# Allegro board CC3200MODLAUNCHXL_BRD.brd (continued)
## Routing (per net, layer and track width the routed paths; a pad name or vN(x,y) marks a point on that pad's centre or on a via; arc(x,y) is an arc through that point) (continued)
CC_GPIO_07: length 91.3
  TOP w0.127: R339.1 44.55,35.38 v1(43.78,35.38) 41.58,35.38 41.2,35.76 U1.52 ; R31.1 1.57,24.89 2.34,25.65 14.94,25.65 v1(15.09,25.5) ; v1(9.11,49.68) 9.11,49.7 7.62,51.18 5.71,51.18 ; v1(43.69,26.54) 43.87,26.36 R300.1
  MID2(L3) w0.127: v1(43.69,26.54) 43.78,26.63 v1(43.78,35.38) ; v1(15.09,25.5) 15.09,26.36 13.86,27.6 13.86,34.72 10.92,37.66 10.92,43.05 9.27,44.7 9.27,49.52 v1(9.11,49.68)
  BOTTOM w0.127: v1(15.09,25.5) 15.38,25.78 15.38,25.79 15.82,26.24 43.38,26.24 v1(43.69,26.54)
CC_GPIO_08: length 35.4
  TOP w0.127: v1(13.34,27.08) 13.34,27.03 13.64,26.72 R278.2 ; U1.53 36.87,37.03 36.58,36.74 v1(36.58,36.48)
  MID2(L3) w0.127: v1(12.52,35.1) 13.34,34.29 v1(13.34,27.08)
  BOTTOM w0.127: v1(12.52,35.1) 12.73,35.31 19.46,35.31 20.8,36.65 36.41,36.65 v1(36.58,36.48)
CC_GPIO_09: length 67.3
  TOP w0.127: v1(43.29,34.49) 44.55,34.49 R334.1 ; v1(43.26,38.3) U1.54 ; R211.1 R212.2 21.72,9.62 v1(21.72,9.62) ; R291.2 14.56,21.89 v1(14.61,21.84)
  MID2(L3) w0.127: v1(43.26,38.3) 43.29,38.27 v1(43.29,34.49) ; v1(14.61,21.84) 14.61,21.8 14.53,21.73 14.53,15.24 20.14,9.62 v1(21.72,9.62)
  BOTTOM w0.127: v1(14.61,21.84) 14.39,22.06 14.39,25.74 15.57,26.92 20.83,26.92 21.37,27.45 37.23,27.45 43.29,33.52 v1(43.29,34.49)
CC_GPIO_10: length 126.1
  TOP w0.127: v1(3.02,20.78) 2.21,20.78 1.57,21.41 R289.1 ; v1(17.55,9.62) R213.2 R210.1 ; U1.3 34.9,40.74 35.26,41.09 36.68,41.09 v1(36.8,40.97) 36.93,41.09 38.41,41.09 40.39,39.12 44.42,39.12 R299.1
  MID2(L3) w0.127: J3.2 41.53,67.77 41.53,64.39 44.45,61.47 44.45,50.16 39.43,45.15 37.91,45.15 36.8,44.04 v1(36.8,40.97) ; v1(10.5,42.62) 10.67,42.45 10.67,37.55 13.6,34.62 13.6,27.42 14.35,26.67 14.35,24.18 12.65,22.48 v1(12.65,20.78) 12.65,10.97 14,9.62 v1(17.55,9.62)
  BOTTOM w0.127: v1(36.8,40.97) 35.36,42.41 26.62,42.41 25.79,41.58 24.03,41.58 22.99,42.62 v1(10.5,42.62) ; v1(12.65,20.78) v1(3.02,20.78)
CC_GPIO_11: length 117.4
  TOP w0.127: R209.1 R214.2 v1(13.72,10.91) ; R290.1 1.57,18.36 1.98,17.96 13.64,17.96 v1(14.1,18.41) ; R298.1 43.33,43.08 41.19,40.94 v1(40.06,40.94) 38.92,40.94 38.48,41.39 34.2,41.39 33.63,40.81 U1.4
  MID2(L3) w0.127: v1(41.19,33.15) 40.87,33.15 40.05,33.97 40.05,40.93 v1(40.06,40.94) 40.26,41.14 40.26,45.59 44.7,50.04 44.7,61.72 41.78,64.64 41.78,70.56 J2.2 ; v1(13.72,10.91) 13.84,10.91 14.1,11.16 v1(14.1,18.41)
  BOTTOM w0.127: v1(41.19,33.15) 41.14,33.15 37.91,29.92 23.47,29.92 20.73,27.18 15.46,27.18 14.14,25.85 14.14,20.26 14.1,20.22 v1(14.1,18.41)
CC_GPIO_12: length 32.2
  TOP w0.127: U1.9 27.28,41.05 26.67,41.66 v1(26.5,41.66) ; R288.1 1.57,35.05 2.03,35.51 v1(3.05,35.51)
  BOTTOM w0.127: v1(3.05,35.51) 4.88,37.34 4.88,39.7 6.22,41.05 12.33,41.05 13.32,42.04 13.34,42.04 13.66,42.36 22.88,42.36 23.92,41.33 26.16,41.33 26.49,41.66 v1(26.5,41.66)
CC_GPIO_13: length 130.9
  TOP w0.127: R287.1 1.57,37.52 2.41,38.35 12.55,38.35 v1(13.74,39.54) ; R111.2 46.84,72.9 42.42,72.9 41.53,72.01 41.53,67.26 J4.1 ; U1.10 26.01,41.61 v1(25.62,42) ; v1(13.68,11.56) 12.57,10.45 12.57,8.76 11.76,7.95 R208.1 SW3.T1
  MID2(L3) w0.127: J4.1 44.3,65.81 47.5,62.61 47.5,50.42 44.2,47.12 44.2,43.69 43.56,43.05 v1(43.56,42.04) ; v1(14.1,43.05) 14.06,43.05 13.74,42.73 v1(13.74,39.54) 13.74,37.44 14.52,36.66 14.52,36.66 14.77,36.42 14.77,36.41 16.76,34.42 16.76,33.3 15.84,32.38 15.84,24.09 13.68,21.93 v1(13.68,11.56)
  BOTTOM w0.127: v1(43.56,42.04) 43.31,42.29 35.94,42.29 35.56,42.67 26.29,42.67 v1(25.62,42) 23.97,42 23.09,42.87 14.28,42.87 v1(14.1,43.05)
CC_GPIO_14: length 45.9
  TOP w0.127: R237.1 1.57,27.48 2.26,28.17 16.31,28.17 v1(16.76,28.62) ; U1.5 32.36,40.87 v1(32.13,41.09)
  MID2(L3) w0.127: v1(16.76,28.62) 16.76,32.3 17.27,32.81 17.27,41.73 v1(17.22,41.78)
  BOTTOM w0.127: v1(17.22,41.78) 17.38,41.95 22.9,41.95 23.77,41.07 32.11,41.07 v1(32.13,41.09)
CC_GPIO_15: length 44.7
  TOP w0.127: R294.2 57.56,27.63 57.56,29.79 R296.2 56.92,30.84 v1(56.64,31.11) ; v1(56.64,43) 55.37,43 54.81,43.56 43.43,43.56 41.27,41.4 38.82,41.4 38.58,41.64 31.79,41.64 31.09,40.94 U1.6
  MID2(L3) w0.127: v1(56.64,43) 56.82,42.82 56.82,31.29 v1(56.64,31.11)
CC_GPIO_16: length 46
  TOP w0.127: U1.7 29.82,40.94 30.77,41.89 38.69,41.89 38.92,41.66 41.15,41.66 43.31,43.81 55.24,43.81 55.52,43.54 v1(56.9,43.54) ; R293.2 56.92,28.75 v1(56.9,28.73) 56.92,28.7 R297.2
  MID2(L3) w0.127: v1(56.9,43.54) 57.07,43.36 57.07,28.91 v1(56.9,28.73)
CC_GPIO_17: length 37.4
  TOP w0.127: R280.2 56.92,37.26 56.39,37.8 v1(56.36,37.8) ; v1(56.16,44.04) 56.13,44.07 43.18,44.07 41.02,41.91 39.03,41.91 38.79,42.15 29.7,42.15 28.55,41 U1.8
  MID2(L3) w0.127: v1(56.36,37.8) 56.36,37.97 55.96,38.38 55.96,43.84 v1(56.16,44.04)
CC_GPIO_22: length 84.9
  TOP w0.127: v1(45.39,44.5) 43.23,44.5 40.92,42.19 39.11,42.19 38.9,42.4 29.61,42.4 29.6,42.42 25.32,42.42 24.74,41.84 U1.11 ; SW2.T1 50.06,1.54 44.97,1.54 R207.1 44.68,1.83 v1(44.68,2.54) ; v1(45.39,17.73) 56.16,17.73 56.92,18.49 R313.2
  MID2(L3) w0.127: v1(45.39,44.5) v1(45.39,17.73) 45.39,17.6 44.68,16.89 v1(44.68,2.54)
CC_GPIO_23: length 54.3
  TOP w0.127: v1(39.22,42.75) 39.14,42.67 23.7,42.67 23.47,42.44 ; 23.47,42.44 17.65,48.26 J10.2 ; 23.47,42.44 U1.12 ; R310.1 v1(41.43,21.89)
  MID2(L3) w0.127: v1(39.22,42.75) 39.37,42.59 39.37,33.99 39.38,33.98 39.38,33.88 41.4,31.86 41.4,21.92 v1(41.43,21.89)
CC_GPIO_24: length 67.5
  TOP w0.127: v1(19.12,37.16) 19.09,37.16 18.96,37.03 U1.18 16.69,37.03 16.15,37.57 16.15,51.21 17.14,52.2 19.68,52.2 J11.2 ; R336.1 44.43,36.84 v1(41.66,36.84) ; v1(43.32,19.3) R311.1
  MID2(L3) w0.127: v1(41.66,36.84) 41.66,33.66 42.23,33.08 42.23,30.61 42.6,30.23 42.6,26.08 43.32,25.36 v1(43.32,19.3)
  BOTTOM w0.127: v1(19.12,37.16) 38.51,37.16 38.83,36.84 v1(41.66,36.84)
CC_GPIO_26: length 66.8
  TOP w0.127: v1(44.02,42.55) 44.37,42.19 R285.1 ; v1(23.41,43.78) 21.97,45.21 21.97,51.44 20.95,52.45 9.55,52.45 5.74,56.26 J5.3 ; v1(19.2,28.27) 19.08,28.14 U1.25
  MID2(L3) w0.127: v1(23.41,43.78) 22.86,43.23 22.86,31.7 19.43,28.27 v1(19.2,28.27)
  BOTTOM w0.127: v1(44.02,42.55) 40.5,42.55 39.88,43.16 24.02,43.16 v1(23.41,43.78)
CC_GPIO_27: length 71.4
  TOP w0.127: R286.1 44.23,40.2 44.2,40.21 v1(41.66,40.21) ; U1.26 18.41,26.87 v1(19.18,27.63) ; J5.4 5.71,58.17 11.18,52.7 21.08,52.7 22.23,51.56 22.23,45.59 v1(24.13,43.69)
  MID2(L3) w0.127: v1(24.13,43.69) 23.11,42.67 23.11,31.57 v1(19.18,27.63) ; v1(41.06,42.96) 41.66,42.37 v1(41.66,40.21)
  BOTTOM w0.127: v1(41.06,42.96) 40.59,42.96 40.13,43.42 24.4,43.42 v1(24.13,43.69)
CC_GPIO_28: length 50.2
  TOP w0.127: R308.1 v1(43.31,29.46) ; v1(42.88,37.52) 43.74,37.52 44.07,37.85 48.44,37.85 49.02,38.43 55.98,38.43 56.39,38.84 56.41,38.84 56.92,39.34 R295.2 ; U1.19 v1(19.12,35.76)
  MID2(L3) w0.127: v1(42.88,37.52) 42.84,37.48 v1(42.84,36.37) 42.82,36.36 42.82,34.37 43.48,33.71 43.48,29.64 v1(43.31,29.46)
  BOTTOM w0.127: v1(42.84,36.37) 38.94,36.37 38.41,36.9 20.26,36.9 v1(19.12,35.76)
CC_GPIO_30: length 24.5
  TOP w0.127: U1.42 36.17,24.54 v1(35.94,24.77) ; R279.2 v1(16.26,24.43)
  BOTTOM w0.127: v1(35.94,24.77) 34.72,25.98 17.85,25.98 16.3,24.43 v1(16.26,24.43)
CC_NRESET: length 99.2
  TOP w0.127: R113.1 15.77,64.77 v1(16.89,64.77) ; U1.35 v1(27.28,24.66) ; v1(43.56,81.41) 43.56,82.08 D9.2 47.07,83.86 SW1.T2 48.68,86.96 47.09,88.55 Q10.1
  MID2(L3) w0.127: v1(27.28,24.66) 27.28,57.25 28.45,58.42 v1(28.45,63.65) ; v1(43.56,81.41) 43.56,77.9 39.12,73.46 39.12,63.75 v1(39.37,63.5)
  BOTTOM w0.127: v1(16.89,64.77) 17.65,64.77 18.92,63.5 28.27,63.5 28.42,63.65 v1(28.45,63.65) 28.6,63.5 v1(39.37,63.5)
DBG_RST_N: length 9
  TOP w0.127: v1(14.61,68.07) 13.08,68.07 12.05,67.04 U9.10 ; U5.19 16.08,70.67 R314.2 16.03,70.26 15.75,69.98 14.99,69.98 14.73,69.72 v1(14.61,69.72)
  BOTTOM w0.127: v1(14.61,69.72) v1(14.61,68.07)
DBGENN: length 26.1
  TOP w0.127: 9.17,81.44 9.11,81.44 8.46,82.09 8.38,82.09 ; 9.17,81.44 8.23,80.49 ; 9.17,81.44 U4.13 ; R317.2 15.11,71.5 v1(14.73,71.88) ; 8.38,82.09 8.69,82.39 R326.2 ; 8.38,82.09 U4.1 ; v1(13.21,78.74) 12.93,79.02 R315.2 12.82,79.49 U4.10 9.26,79.49 8.26,80.49 8.23,80.49 ; 8.23,80.49 8.23,80.49 7.87,80.14 U4.4
  BOTTOM w0.127: v1(13.21,78.74) 14.61,77.34 14.61,72.01 v1(14.73,71.88)
DBGMOD: length 17.6
  TOP w0.127: U4.2 v1(7.26,81.44) ; R316.2 14.86,72.75 14.86,74.04 12.95,75.95 12.95,76.64 12.38,77.22 10.03,77.22 7.76,79.49 v1(7.75,79.49) U4.5
  BOTTOM w0.127: v1(7.26,81.44) 7.75,80.95 v1(7.75,79.49)
FT_CS: length 16.4
  TOP w0.127: v1(10.26,72.11) U7.9 13.24,72.11 13.97,71.37 13.97,69.72 14.48,69.22 15.09,69.22 R306.2 ; v1(7.62,72.14) 7.62,67.94 6.72,67.04 U9.5
  BOTTOM w0.127: v1(7.62,72.14) 7.65,72.11 v1(10.26,72.11)
FT_DI: length 13.1
  TOP w0.127: U7.11 11.3,73.53 10.03,73.53 9.53,73.03 9.53,68.58 10.41,67.69 U9.11 12.06,67.69 12.95,68.58 15.09,68.58 R305.2
FT_DO: length 25.5
  TOP w0.127: v1(10.16,78.74) 10.26,78.84 U4.9 ; R304.2 13.46,67.44 v1(13.34,67.31) ; U7.2 4.67,74.71 4.32,75.06 4.32,76.33 4.83,76.83 7.49,76.83 v1(8.51,77.85)
  BOTTOM w0.127: v1(13.34,67.31) 13.34,67.56 12.19,68.71 12.19,75.16 11.18,76.17 11.18,77.72 v1(10.16,78.74) 9.4,78.74 v1(8.51,77.85)
FT_SK: length 19.9
  TOP w0.127: v1(14.99,65.76) R303.2 ; U4.12 9.97,80.79 v1(9.91,80.72)
  BOTTOM w0.127: v1(9.91,80.72) 12.45,78.18 12.45,68.83 14.99,66.29 v1(14.99,65.76)
FTDI_RX: length 6.5
  TOP w0.127: R330.2 25.39,61.94 25.39,63.49 27.76,65.87 R333.2
FTDI_TX: length 12.1
  TOP w0.127: R332.2 25.64,63.39 25.64,59.09 24.4,57.85 U11.4
JTAG_TCK: length 22
  TOP w0.127: v1(15.98,33.63) 16.39,33.22 U1.21 ; v1(11.56,47.93) R13.1 J8.2
  MID2(L3) w0.127: v1(11.56,47.93) 11.56,37.77 15.7,33.63 v1(15.98,33.63)
JTAG_TMS: length 22.7
  TOP w0.127: U1.22 18.54,31.95 19.13,32.54 19.13,33.63 18.9,33.86 17.2,33.86 15.9,35.15 15.9,50.14 J9.2
LP_GPIO_01: length 58.2
  TOP w0.127: R284.2 56.92,22.63 v1(56.87,22.68) ; v1(57.33,44.4) 56.77,44.96 43.18,44.96 41.87,43.65 31.53,43.65 28.85,46.33 28.85,50.52 J7.1
  MID2(L3) w0.127: v1(57.33,44.4) 57.33,23.14 v1(56.87,22.68)
LP_GPIO_02: length 19.1
  TOP w0.127: v1(14.22,37.95) 13.64,37.37 R309.2
  MID2(L3) w0.127: J6.1 24.41,51.18 14.22,41 v1(14.22,37.95)
LP_GPIO_25: length 43.3
  TOP w0.127: R36.2 56.92,24.89 56.16,25.65 44.09,25.65 v1(44.04,25.7) ; v1(43.07,31.67) 44.53,31.67 R337.1
  MID2(L3) w0.127: v1(44.04,25.7) 43.43,25.7 42.88,26.26 42.88,30.45 43.07,30.65 v1(43.07,31.67) 43.07,33.77 42.57,34.26 42.57,34.26 42.42,34.42 42.42,45.72 46.23,49.53 J14.1
LP_RESET_OUT: length 66.7
  TOP w0.127: D9.1 47.09,81.29 R226.2 47.12,78.87 v1(46.46,78.21) ; v1(44.86,32.66) 45.36,32.66 45.97,33.27 55.85,33.27 56.39,32.74 v1(56.39,32.72) 56.41,32.72 56.92,32.21 R292.2
  MID2(L3) w0.127: v1(46.46,78.21) 45.21,76.96 45.21,65.28 47.75,62.74 47.75,50.29 44.45,46.99 44.45,42.63 44.63,42.45 44.63,32.89 v1(44.86,32.66)
RF_BG: length 13.5
  TOP w0.508: U1.31 22.2,22.3 arc(22.44,19.8) 23.14,17.39 arc(24.09,15.47) 25.33,13.73 arc(25.7,13.32) 26.09,12.91 R75.1
SENS_I2C_SCL: length 12.2
  TOP w0.127: R172.1 R97.1 ; R172.1 49.25,69.44 49.91,70.1 51.59,70.1 R107.1 ; R172.1 47.12,68.45 46.71,68.86 J3.1
SENS_I2C_SDA: length 22.4
  TOP w0.127: R104.1 R173.1 48.79,65 46.35,67.44 42.55,67.44 41.78,68.2 41.78,70.71 J2.1 44.17,70.71 R108.1
SOP0: length 65.4
  TOP w0.127: v1(26.04,24.89) 26.01,24.87 U1.34 ; v1(53.47,55.79) 53.47,55.98 53.98,56.49 R4.1 54.61,55.98 54.61,52.84 J17.1
  MID2(L3) w0.127: v1(26.8,49.53) 26.92,49.4 26.92,25.78 v1(26.04,24.89)
  BOTTOM w0.127: v1(53.47,55.79) 53.34,55.92 30.64,55.92 29.46,54.75 29.46,50.67 28.32,49.53 v1(26.8,49.53)
SOP1: length 61.4
  TOP w0.127: v1(46.23,56.39) 46.33,56.49 R7.1 51.18,55.5 51.56,55.12 51.56,52.84 J16.1 ; U1.24 v1(19.26,29.41)
  MID2(L3) w0.127: v1(46.23,56.39) 44.96,55.12 44.96,49.91 40.51,45.47 40.51,40.05 40.35,39.89 40.35,34.28 40.84,33.78 v1(40.87,33.78)
  BOTTOM w0.127: v1(19.26,29.41) 20.06,30.21 37.84,30.21 40.77,33.14 40.77,33.68 v1(40.87,33.78)
SOP2/TCXO_EN: length 58.1
  TOP w0.127: v1(46.61,55.37) 47.24,56.01 R8.1 48.62,52.74 J15.1 ; R12.2 15.6,31.57 16.23,32.2 v1(16.26,32.2)
  MID2(L3) w0.127: v1(16.26,32.2) 17.02,32.97 17.02,41.26 16.76,41.52 16.76,42.24 23.24,48.72 v1(23.24,48.77)
  BOTTOM w0.127: v1(23.24,48.77) 27.94,48.77 29.72,50.55 29.72,54.64 30.7,55.63 46.35,55.63 v1(46.61,55.37)
SRSTN: length 0.8
  TOP w0.127: R327.2 R113.2
TEMP_INTR: length 4.6
  TOP w0.127: R111.1 49.4,71.88 50.42,72.9 50.42,74.17 50.93,74.68 U6.C2
USB_D+: length 18.4
  TOP w0.152: J1.3 v1(11.94,86.89) ; R28.1 21.59,78.64 21.59,79.2 21.71,79.32 21.84,79.32 ; v1(21.84,80.06) 21.84,79.32 ; 21.84,79.32 D14.1
  BOTTOM w0.152: v1(21.84,80.06) 21.62,79.83 21.62,79.39 21.25,79.02 18.05,79.02 12.13,84.93 12.13,86.7 v1(11.94,86.89)
USB_D-: length 17.4
  TOP w0.152: J1.2 v1(12.59,86.89) ; v1(21.09,80.04) 21.09,79.38 D13.1 21.19,79.32 21.31,79.2 21.31,78.64 R343.1
  BOTTOM w0.152: v1(21.09,80.04) 21.34,79.79 21.34,79.5 21.13,79.3 18.16,79.3 12.41,85.05 12.41,86.72 v1(12.59,86.89)
USB_DM: length 2.5
  TOP w0.152: R343.2 21.33,77.2 21.33,76.13 21.22,76.02 U5.8
USB_DP: length 6.3
  TOP w0.152: v1(22.48,77.52) R28.2 21.61,77.24 21.61,76.13 21.72,76.02 U5.7 ; R345.1 v1(24.56,78.46)
  BOTTOM w0.152: v1(24.56,78.46) 24.56,78.46 23.62,77.52 v1(22.48,77.52)
N185612: length 8.3
  TOP w0.127: R103.1 R98.1 53.07,68.95 U10.7 53.43,67.61 53.75,67.28 C50.1 54.23,65.64 53.51,64.92 C52.1 52.57,65.05 U10.3
N185801: length 3.5
  TOP w0.254: C51.1 54.95,74.18 U6.A3
  TOP w0.305: R101.1 C51.1
N186121: length 1.5
  TOP w0.127: R102.2 50.15,66 U10.1
N186159: length 2.1
  TOP w0.127: R103.2 51.16,67.34 51.44,67.05 U10.11
N186206: length 1.7
  TOP w0.127: R97.2 50.69,66.55 U10.12
N186210: length 2.4
  TOP w0.127: U10.2 52.07,65.41 51.31,64.64 R104.2
N187169: length 3.6
  TOP w0.127: U6.C1 51.28,75.21 R99.1 R72.2
N187173: length 3.8
  TOP w0.127: R86.1 R106.2 U6.B1
N187525: length 2.8
  TOP w0.127: R107.2 51.82,71.91 U6.B3
N187543: length 2.8
  TOP w0.127: U6.C3 51.32,71.79 R108.2
N187626: length 14.6
  TOP w0.127: v1(53.72,66.42) 53.59,66.55 U10.5
  BOTTOM w0.127: v1(53.72,66.42) 53.21,66.93 41.55,66.93 J4.2
N195183: length 1.5
  TOP w0.127: D4.1 31.86,87 R64.2
N195451: length 4.2
  TOP w0.508: R55.2 R56.1 C31.2 22.02,86.56 22.33,86.87 U3.4
N292143: length 2.4
  TOP w0.635: 51.41,8.38 52.07,9.04 J20.1 51.51,9.75 50.95,9.75
N311613: length 4.2
  TOP w0.127: R225.2 56.9,87.04 55.59,85.72 SW1.T1
N311877: length 6.5
  TOP w0.127: R168.2 9.32,6.27 7.11,4.06 SW3.T2
N311889: length 5.6
  TOP w0.127: SW2.T2 50.06,6.54 45.99,6.54 45.59,6.93 R169.2
N312530: length 1.4
  TOP w0.254: R94.1 22.56,2.7 D7.2
N312602: length 1.6
  TOP w0.254: D5.2 13.09,3.49 R69.1
N312606: length 1.8
  TOP w0.254: R70.1 17.09,3.21 D6.2
N312650: length 1.6
  TOP w0.127: R94.2 23.93,5.43 Q9.3
N312654: length 1.6
  TOP w0.127: Q8.3 18.72,5.58 18.72,4.45 R70.2
N312670: length 2.1
  TOP w0.127: R69.2 15.04,4.44 Q7.3
N312782: length 1.4
  TOP w0.127: R209.2 14.79,8.75 Q7.1
N312798: length 1.4
  TOP w0.127: R210.2 19.62,8.75 Q8.1
N312802: length 1.9
  TOP w0.127: R211.2 24.16,8.81 24.75,8.22 Q9.1
N329065: length 1.4
  TOP w0.254: R277.2 Q11.1
N394921: length 1.9
  TOP w0.406: L11.2 35.29,80.25 U8.5
N487570: length 2.7
  TOP w0.254: U5.6 22.22,76.02 22.28,76.07
  TOP w0.406: C54.1 23.32,76.61 22.76,76.61 22.28,76.12 22.28,76.07
N487672: length 3.3
  TOP w0.254: R338.1 27.89,73.13 C55.1 27.43,72.67 U5.46
N487804: length 3.1
  TOP w0.127: U5.5 22.72,75.93 22.96,76.17 23.9,76.17 24.56,76.83 R345.2
N487824: length 1.8
  TOP w0.254: U5.26 19.72,64.94 R34.2
N487832: length 2.2
  TOP w0.127: U5.10 20.22,76.45 R30.2
N487932: length 3.1
  TOP w0.127: R333.1 27.76,68.4 27,69.17 U5.39
N488104: length 3.9
  TOP w0.127: U5.40 26.88,69.67 28.65,67.89 R332.1
N488180: length 10.4
  TOP w0.127: U2.2 30.23,81.77 29.97,81.51 R342.2 29.43,79.76 25.57,75.9 24.85,75.9 U5.1
N488188: length 10.6
  TOP w0.127: U2.1 R32.2 31.09,79.73 31.09,79.73 30.71,79.73 30.48,79.5 30.48,78.74 30.1,78.36 28.4,78.36 26.22,76.18 U5.48
N488454: length 2.1
  TOP w0.127: U5.24 R303.1
N488458: length 2.4
  TOP w0.127: U5.23 16.98,68.67 16.03,67.72 R304.1
N488478: length 6.2
  TOP w0.127: U2.4 30.26,83.07 29.46,82.27 29.46,81.41 28.09,80.04 28.09,79.88 R35.1 R302.2
N488614: length 11.4
  TOP w0.127: U5.2 24.22,75.97 24.4,76.15 25.47,76.15 28.73,79.41 R35.2 28.91,79.71 29.72,80.52 29.72,81.94 30.2,82.42 U2.3
N488778: length 9
  TOP w0.127: Y1.2 31.75,69.55 30.86,70.43 C60.1 28.12,70.43 27.39,71.17 U5.43
N488782: length 9.4
  TOP w0.127: Y1.1 31.75,72.01 31.01,71.27 C59.1 27.71,71.27 27.32,71.67 U5.44
N489641: length 2
  TOP w0.127: U5.22 16.94,69.17 16.23,68.45 R305.1
N489651: length 1.8
  TOP w0.127: R306.1 16.35,69.67 U5.21
N490596: length 3.1
  TOP w0.508: FB12.1 10.21,87.15 10.64,87.57 J1.5
N507782: length 1.8
  TOP w0.127: U5.17 16.89,71.67 16.72,71.5 R317.1
N507786: length 1.8
  TOP w0.127: U5.16 16.25,72.17 R316.1
N508362: length 20.3
  TOP w0.127: U9.13 v1(10.29,68.99) ; v1(4.06,77.98) 4.06,78.71 R318.2 4.19,78.84 U4.6 ; U9.4 6.48,67.69 6.6,67.82 v1(6.73,67.82)
  BOTTOM w0.127: v1(10.29,68.99) 9.11,67.82 v1(6.73,67.82) 6.1,67.82 4.57,69.34 4.57,77.47 v1(4.06,77.98)
N508615: length 14.3
  TOP w0.127: U7.13 10.38,74.71 v1(10.29,74.8) ; R319.1 4.05,80.79 U4.3 6.69,80.79 v1(6.71,80.77) ; U7.10 10.56,72.76 v1(10.29,73.03)
  BOTTOM w0.127: v1(10.29,73.03) v1(10.29,74.8) 10.29,75.06 6.71,78.64 v1(6.71,80.77)
N509670: length 1.8
  TOP w0.127: R320.1 12.29,80.14 U4.11
N509674: length 1.7
  TOP w0.127: U4.8 13.02,78.19 R321.1
N511498: length 14.5
  TOP w0.127: R322.1 3.99,66.39 U9.6 6.96,66.39 8.51,67.94 8.51,73.53 6.69,75.36 U7.1
N512182: length 14.8
  TOP w0.127: R323.1 3.85,74.06 U7.3 v1(6.72,74.06) ; U7.8 10.41,71.46 v1(10.31,71.35) 9.78,70.82 9.78,68.71 10.15,68.34 U9.12
  BOTTOM w0.127: v1(10.31,71.35) 7.13,71.35 6.72,71.77 v1(6.72,74.06)
N512199: length 1.8
  TOP w0.127: R324.1 13.2,74.06 U7.12
N517852: length 1.6
  TOP w0.127: R325.1 13.03,66.39 U9.9
N517913: length 1.6
  TOP w0.127: R326.1 D2.2
N518669: length 1.9
  TOP w0.127: U9.8 12.34,65.74 R327.1
N519131: length 1.8
  TOP w0.127: R329.1 3.85,72.76 U7.5
N519138: length 1.6
  TOP w0.127: U9.2 3.99,68.99 R328.1
N16837579: length 9.7
  TOP w0.508: J16.2 52.32,53.6 R9.2
  BOTTOM w0.508: J15.2 J16.2 J17.2
N16966302: length 51.5
  TOP w0.127: v1(17.18,32.13) 16.89,32.13 16.41,31.65 R12.1 16.46,30.68 U1.23
  MID2(L3) w0.127: v1(24,48.26) 23.16,48.26 17.64,42.74 17.64,32.59 v1(17.18,32.13)
  BOTTOM w0.127: v1(24,48.26) 24.26,48.51 28.07,48.51 29.97,50.42 29.97,54.54 30.81,55.37 44.45,55.37 J14.2
N17067937: length 3.9
  TOP w0.127: R291.1 J22.18
N17067943: length 4
  TOP w0.127: J22.9 2.47,32.05 R231.2
N17067945: length 4
  TOP w0.127: J22.13 2.47,26.97 R237.2
N17067955: length 4.2
  TOP w0.127: J22.14 9.27,26.59 12.57,26.59 R278.1
N17067957: length 3.9
  TOP w0.127: R279.1 J22.16
N17067979: length 4.1
  TOP w0.127: J23.6 52.12,37.08 R280.1
N17067993: length 4.1
  TOP w0.127: J23.18 56.06,21.89 R284.1
N17068333: length 4.1
  TOP w0.127: R341.1 56.06,34.59 J23.8
N17068401: length 18.7
  TOP w0.127: U12.3 17.74,61.28 R347.1 17.14,60.68 17.14,57.66 19.81,54.99 26.92,54.99 J7.3
N17068413: length 4.2
  TOP w0.127: J22.10 9.37,31.57 12.78,31.57 R346.1
N17068423: length 3.9
  TOP w0.127: R340.1 J22.12
N17068425: length 1.3
  TOP w0.127: U12.4 23.78,61.28 R330.1
N17068635: length 4
  TOP w0.127: R10.2 2.47,39.67 J22.3
N17068637: length 4
  TOP w0.127: J22.19 2.44,19.35 R290.2
N17068639: length 4
  TOP w0.127: R287.2 2.47,37.13 J22.5
N17068641: length 4
  TOP w0.127: R288.2 2.47,34.59 J22.7
N17068645: length 4.1
  TOP w0.127: R31.2 2.31,24.43 J22.15
N17068647: length 4
  TOP w0.127: J22.17 2.44,21.89 R289.2
N17068649: length 4.5
  TOP w0.127: J6.3 20.83,56.26 20.6,56.49 R331.1
N17068681: length 1.4
  TOP w0.127: R331.2 19.79,57.79 U11.3
N17068737: length 6.3
  TOP w0.127: R339.2 R334.2 R344.2 45.62,33.6 48.54,33.6 J23.7
N17068769: length 4.1
  TOP w0.127: R36.1 55.96,24.43 J23.16
N17068771: length 5.8
  TOP w0.127: J23.14 56.08,26.97 R297.1 R294.1
N17068783: length 4.1
  TOP w0.127: R295.1 52.12,39.62 J23.4
N17068785: length 4.1
  TOP w0.127: J23.10 56.06,32.05 R292.1
N17068787: length 4.9
  TOP w0.127: R296.1 R293.1 56.08,29.51 J23.12
N17068892: length 4.9
  TOP w0.127: R299.2 R286.2 49.5,39.7 J23.3
N17068894: length 4.2
  TOP w0.127: J23.5 49.36,36.96 R336.2
N17068898: length 5
  TOP w0.127: R307.2 R337.2 49.3,31.82 J23.9
N17068900: length 4.1
  TOP w0.127: R308.2 49.48,29.46 J23.11
N17068902: length 4.3
  TOP w0.127: J23.13 48.92,26.36 R300.2
N17068904: length 4
  TOP w0.127: R301.2 47.14,24.43 J23.15
N17068906: length 4
  TOP w0.127: J23.17 R310.2
N17068908: length 4.1
  TOP w0.127: R311.2 49.48,19.3 J23.19
N17068924: length 5
  TOP w0.127: J23.1 49.5,42.19 R285.2 R298.2
N17069150: length 3.9
  TOP w0.127: J22.6 R309.1
N17069152: length 4
  TOP w0.127: J22.8 9.14,34.34 R312.1
N17069176: length 4
  TOP w0.127: J22.11 2.36,29.51 R22.2
N17069198: length 4.1
  TOP w0.127: J23.20 56.06,19.35 R313.1
N17069292: length 3.9
  TOP w0.127: R335.1 J22.20
N17097905: length 1.5
  TOP w0.127: D1.2 39.91,85.09 R95.1
N17097907: length 1.6
  TOP w0.127: Q10.3 42.72,86.66 R95.2
N17123437: length 4.5
  TOP w0.508: J18.1 32.28,13.59 L6.1 29.14,13.59 C73.2
N17123480: length 0.9
  TOP w0.508: C73.1 R74.1
N17123972: length 2.2
  TOP w0.127: 29.99,9.01 J24.4 R77.2
  TOP w0.254: 30.05,8.95 R77.2
  TOP w0.508: L4.1 30.99,8.01 L5.1 30.05,8.95 29.99,9.01
N17134004: length 2.5
  TOP w0.508: L4.2 32.42,6.59 C64.2 32.54,6.47 arc(32.82,6.12) 33.01,5.71 33.02,5.69 arc(33.08,5.44) E1.1
N17134874: length 1
  TOP w0.305: J24.1 28.52,10.5 28.47,10.55
  TOP w0.508: R75.2 28.47,10.55
N17156940: length 1
  TOP w0.127: 29.48,9.52 29.55,9.45 29.55,9.44 ; R76.1 28.98,10.01
  TOP w0.508: 28.98,10.01 29.48,9.52

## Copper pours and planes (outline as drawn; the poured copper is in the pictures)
GND on TOP (solid shape): 33.36,1.78 35.17,1.78 35.17,0.58 31.86,0.58 31.86,1.78 32.86,1.78 32.86,5.44 33.36,5.44
GND on TOP: 2.03,0.25 0.77,0.77 0.25,2.03 0.25,91.95 0.77,93.21 2.03,93.73 56.39,93.73 57.65,93.21 58.17,91.95 58.17,2.03 57.65,0.77 56.39,0.25 37.85,0.25 37.85,5.46 31.88,5.46 31.88,0.25 ; 2 cut-outs
GND on BOTTOM, MID1(L2), MID2(L3): 2.03,0.25 0.77,0.77 0.25,2.03 0.25,91.95 0.77,93.21 2.03,93.73 56.39,93.73 57.65,93.21 58.17,91.95 58.17,2.03 57.65,0.77 56.39,0.25 37.85,0.25 37.85,5.46 31.88,5.46 31.88,0.25
VBAT_CC on MID2(L3) (solid shape): 32.66,23.44 32.66,22.37 32.41,22.12 30.38,22.12 30.25,22.25 30.25,23.36 30.45,23.57 32.54,23.57
VBAT_CC on TOP: 34.58,52.25 34.72,52.1 42.04,52.1 42.42,51.72 42.42,49.91 42.04,49.53 38.86,49.53 38.84,49.55 33.32,49.55 33.31,49.53 30.61,49.53 29.97,50.16 29.97,52.07 30.15,52.25
VBUS_USB1 on TOP: 26.26,85.42 25.37,84.53 23.8,84.53 23.79,84.53 17.09,84.53 16.9,84.33 15.44,84.33 15.44,85.62 15.49,85.67 22.53,85.67 22.76,85.9 24.77,85.9 25.25,86.39 25.25,89.66 24.54,90.37 22.73,90.37 22.72,90.38 22.72,90.98 22.78,91.05 25.23,91.05 26.26,90.02
VBUS_USB1 on MID2(L3): 24.2,70.43 25.19,70.43 25.43,70.66 25.43,72.58 29.04,76.19 29.04,84.25 27.26,86.03 24.74,86.03 24.43,85.72 24.43,84.61 26.62,82.42 26.62,77.77 22.92,74.07 22.92,71.7
VCC_BRD on TOP: 48.06,7.67 48.06,10.36 47.98,10.44 46.71,10.44 46.58,10.31 46.58,8.38 46.23,8.03 46.23,7.62 46.37,7.48 47.86,7.48
VCC_BRD on TOP: 29.97,53.21 29.97,54.86 30.48,55.37 34.04,55.37 34.8,54.61 34.8,53.34 34.42,52.96 30.23,52.96
VCC_BRD on TOP: 39.19,83.84 37.64,83.84 37.49,83.69 37.49,83.23 37.57,83.16 38.85,83.16 39.25,82.75 39.25,82 38.91,81.66 37.57,81.66 37.49,81.58 37.49,81.38 37.64,81.23 39.26,81.23 40.11,82.08 41.94,82.08 42.06,82.19 42.06,83.13 41.94,83.26 39.78,83.26
VCC_BRD on MID2(L3): 32.13,52.07 33.91,52.07 35.94,50.04 43.69,50.04 44.07,50.42 44.07,51.94 43.56,52.45 42.16,52.45 38.73,55.88 38.73,81.05 39.75,82.07 43.84,82.07 47.75,78.16 47.75,63.63 48.55,62.83 48.55,50.39 46.8,48.64 46.8,7.61 46.92,7.48 48.11,7.48 48.21,7.57 48.21,43.81 56.13,51.74 56.13,79.5 48.56,87.08 35.75,87.08 35.56,86.89 35.56,63.37 31.62,59.44 31.62,52.58
VCC_LDO_3V3 on TOP: 24.18,89.61 21.95,89.61 21.34,89 21.34,87.86 21.26,87.78 21.26,87.18 21.31,87.13 22.06,87.13 22.47,87.53 22.47,88.76 22.86,89.15 24.18,89.15 24.28,89.26 24.28,89.51
VCC_LDO_3V3 on TOP: 26.47,59.91 26.62,59.76 36.11,59.76 36.12,59.77 40.82,59.77 42.04,58.55 42.04,54.86 42.29,54.61 44.07,54.61 44.45,54.99 44.45,59.31 42.51,61.24 26.82,61.24 26.47,60.89
VCC_LDO_3V3 on MID2(L3): 16.93,66.69 8.06,66.69 5.84,68.91 5.84,82.3 6.54,82.99 8.57,82.99 8.58,83.01 11.41,83.01 17.09,77.32 20.83,77.32 23.09,79.58 23.09,80.29 21.2,82.18 21.2,87.98 21.49,88.27 22.84,88.27 23.09,88.02 23.09,85.22 26.34,81.96 26.34,77.85 21.18,72.69 21.18,67.05 24.78,63.45 24.79,63.45 27.47,60.77 27.47,59.96 27.2,59.69 23.93,59.69
Net_42 on TOP (solid shape): outline of 202 points within -199.64,-7.28 -195.12,-2.76
Net_43 on BOTTOM (solid shape): outline of 202 points within -194.64,-7.28 -190.12,-2.76
Net_44 on TOP (solid shape): outline of 202 points within -199.64,96.72 -195.12,101.24
Net_45 on BOTTOM (solid shape): outline of 202 points within -194.64,96.72 -190.12,101.24
Net_46 on BOTTOM (solid shape): outline of 202 points within 32.33,-7.28 36.85,-2.76
Net_47 on TOP (solid shape): outline of 202 points within 37.34,-7.28 41.86,-2.76
Net_48 on BOTTOM (solid shape): outline of 201 points within 32.33,96.72 36.85,101.24
Net_49 on TOP (solid shape): outline of 202 points within 37.34,96.72 41.86,101.24
N292143 on TOP: 51.61,8.05 51.92,8.36 51.92,9.8 51.66,10.06 50.45,10.06 50.28,10.24 50.28,11.27 50.15,11.39 48.93,11.39 48.61,11.39 48.51,11.3 48.51,8.26 48.72,8.05
N490588 on TOP: 13.06,88.93 13.06,87.6 13.56,87.1 13.56,85.06 13.82,84.81 14.78,84.81 14.86,84.89 14.86,86.18 14.73,86.31 14.73,88.32 14,89.05 13.18,89.05

Small or netless copper shapes (teardrops, artwork), in the pictures only: 1 on TOP

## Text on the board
BOTTOM: BOTTOM
Board Geometry/Soldermask Bottom: BOTTOM_SOLDERMASK
Package Geometry/Pastemask Bottom: Bottom Side Reflow | Bottom Origin
Ref Des/Silkscreen Bottom: BOTTOM_SILKSCREEN
User.Comments: 10.MATERIAL : | 11.PLATING : | 12.PCB Outline Dimension Tol: | 1. PCB VENDOR MUST BE UL  QUALIFIED | 2. BOARD MUST BE IDENTIFIED WITH APPROPRIATE VENDOR UL IDENTIFACTION MARK,DATE CODE | 3. PCB MATERIAL UL FLAMMIBILITY RATING(94V-0 MINIMUM) | 4. ALL DIMESION TOLERANCE AS BELOW UNLESS OTHERWISE SPECIFIED. | 5. PCB LAYERS : | 6. PCB THICKNESS : | 7. | 8. TOP SIDE SILKSCREEN : | 9. SOLDER MASK : | NOTES: | TRACE WIDTHS TO BE FINISHED SIZES+/-1MIL | BOTTOM SIDE SILKSCREEN: | OSP 0.2-0.6um[8-24uinch]) | HF_FR4 | 4 LAYERs | RED | 1.2 mm+/-0.12 mm | TG: | ,BOTH SIDES | WHITE | 150 | ROUTING : | CELSIUS | +/- 0.13mm | 1.7 +/-0.4 mil(H/1oz Finished) | 1.2 +/-0.2 mil(1oz) | (0.4~1.2mil) | TOP
TOP: TOP
Board Geometry/Soldermask Top: TOP_SOLDERMASK
Package Geometry/Pastemask Top: Top Origin | Top Side Reflow
Ref Des/Silkscreen Top: DBGENn | GND | 5V | P58 | P04 | P03 | P61 | P59 | P05 | P62 | P01 | P02 | VCC | MAC | NWP | P30(G27) | P29(G26) | P60 | P57 | P63 | P53 | P64 | P50 | TCK | P4(GP13) | TMS | TDI | TDO | RX | TX | PWR | CC | 3.3V | P15(GP22) | FOR P21->BP | SHORT J14 | P18 | P16 | P17 | P30 | P21 | P29 | BRD | EMU | SDA | SCL | INT | J15 | 001:2W SWD | 000:4W JTAG | 100:FLASH | J16 | P08 | P45 | RST | P06 | P07 | P55 | P15 | 2XAA | J17 | P2(GP11) | P1(GP10) | BP | FLASH | P64(GP09) | SOP | 2 | 1 | 0 | Rev 4.1 | P4 | SENSORS | RESET | P2 | CC3200MODLAUNCHXL | LAUNCHPAD | TOP_SILKSCREEN
MID1(L2): MID1(L2)
MID2(L3): MID2(L3)
PAGE_OUTLINE: Scale 1000mil | Layer name | PCB P/N | Rev. | Texas Instruments | 308.01741 | 015
DISPLAY_TOP: 1 | Top Side Reflow | Bottom Side Reflow | UNIT :MM | *Reference CNSBG Break-Away rule | Cavity_Number
MECH 11(SINGLE): 94 | 50.8 | UNIT :MM
User.7: J2 | J3 | J4 | R37 | R54 | R55 | R47 | R48 | R51 | R288 | R42 | R43 | R27 | C11 | R31 | R32 | R38 | R23 | U6 | R39 | U10 | C21 | R24 | C17 | SDA | INT | SCL | SENSORS
User.11: MID3(L4)
User.12: MID4(L5)
User.13: MID5(L6)
User.14: MID6(L7)
User.15: MID7(L8)
User.16: MID8(L9)
User.17: MID9(L10)
User.18: MID11(L12)
User.19: MID12(L13)
User.22: BOTTOM_PASTE
User.23: TOP_PASTE
User.26: NCDRILL
User.35: FIGURE | SIZE | 10.0 | 39.0 | 43.0 | 157.0 | 58.0x19.0 | DRILL CHART: TOP to BOTTOM | ALL UNITS ARE IN MILS | TOLERANCE | +3.0/-3.0 | +4.0/-0.0 | +4.0/-4.0 | PLATED | NON-PLATED | QTY | 1081 | 57 | 26 | 4
